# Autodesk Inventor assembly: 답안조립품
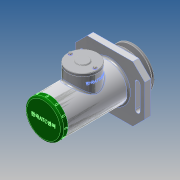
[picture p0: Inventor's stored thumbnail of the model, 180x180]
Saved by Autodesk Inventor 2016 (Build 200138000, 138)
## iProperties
Created: 2017-10
Part Number: 답안조립품
Document SubType Name: Assembly
Designer: Administrator
Author: Administrator
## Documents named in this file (20)
- C:\Users\Administrator\Desktop\471007V1006\답안조립품.iam
- C:\Users\Administrator\Desktop\471007V1006\본체.ipt
- C:\Users\Administrator\Desktop\471007V1006\V-벨트풀리.ipt
- C:\Users\Administrator\Desktop\471007V1006\너트 M10.ipt
- C:\Users\Administrator\Desktop\471007V1006\멈춤링 15 x 1.ipt
- C:\Users\Administrator\Desktop\471007V1006\멈춤링 35x1.6.ipt
- C:\Users\Administrator\Desktop\471007V1006\베어링 15 x 35 x 11.ipt
- C:\Users\Administrator\Desktop\471007V1006\볼트 M4 x 10.ipt
- C:\Users\Administrator\Desktop\471007V1006\부시1.ipt
- C:\Users\Administrator\Desktop\471007V1006\부시2.ipt
- C:\Users\Administrator\Desktop\471007V1006\사이드 커버.ipt
- 사이드 커버.ipt
- C:\Users\Administrator\Desktop\471007V1006\십자볼트 M3 x 10.ipt
- C:\Users\Administrator\Desktop\471007V1006\오일 실 15 25 7.ipt
- C:\Users\Administrator\Desktop\471007V1006\와셔 3x6.ipt
- C:\Users\Administrator\Desktop\471007V1006\와셔 4x16.ipt
- C:\Users\Administrator\Desktop\471007V1006\와셔 10x21.ipt
- C:\Users\Administrator\Desktop\471007V1006\축.ipt
- C:\Users\Administrator\Desktop\471007V1006\키 4 x 4 x 18.ipt
- C:\Users\Administrator\Desktop\471007V1006\탑 커버.ipt
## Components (2 placed, 2 different names)
1. V-벨트풀리:1 — 각도:1
2. ISO 4017 M4 x 10:1
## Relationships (1: Angle 1)
- 각도:1 [Angle]: V-벨트풀리:1
## Named parameters: d35_d32 = 0, d36_d31 = 0
